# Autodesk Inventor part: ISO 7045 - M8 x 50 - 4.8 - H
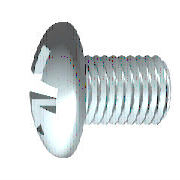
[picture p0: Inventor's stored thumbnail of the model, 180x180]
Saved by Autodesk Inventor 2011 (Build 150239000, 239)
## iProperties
IsCustomPart: 0
Created: 2010-02
Part Number: ISO 7045 - M8 x 50 - 4.8 - H
Material: Stainless Steel, 440C
Description: Cross Recessed Pan Head Machine Screw
Document SubType Name: Modeling
Standard: ISO 7045
Designer: R. Koolhoven
Standard Revision: 1994
Standards Organization: DIN
Language: en-US
Size Designation: M8 x 50 - 4.8 - H
Categories: <MemberInstance><Categories><Category DisplayName="Fasteners" InternalName="e4da775c-781d-43d5-af7c-5136215cf5a6" Mnemonic="FSTN"><Category DisplayName="Bolts"
Density: 7.75 g/cm^3
Mass: 25.2934 g
Surface Area: 18.7499 cm^2
Volume: 3.26367 cm^3
Author: R. Koolhoven
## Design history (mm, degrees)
body "Solid1"
workplane "Work Plane3"
sketch "Sketch2"
  geometry: L1 (-11.037, 0)-(11.037, 0) reference; L2 (0, -11.037)-(0, 11.037) reference; L3 (0, 4.5)-(0, 0); L4 (0, 0)-(4.5, 0); L5 (0, 0)-(5.574, 5.574); L6 (1.21, 4.334)-(0.822, 1.343); L7 (4.334, 1.21)-(1.343, 0.822); L8 (1.21, -4.334)-(0.822, -1.343); L9 (4.334, -1.21)-(1.343, -0.822); L10 (-1.21, 4.334)-(-0.822, 1.343); L11 (-4.334, 1.21)-(-1.343, 0.822); L12 (-4.334, -1.21)-(-1.343, -0.822); L13 (-1.21, -4.334)-(-0.822, -1.343); A1 r 1.35 centre (0, 0) between (1.35, 0) and (0, 1.35); A2 r 4.5 centre (0, 0) between (4.5, 0) and (4.334, 1.21); A3 r 4.5 centre (0, 0) between (1.21, 4.334) and (0, 4.5); A4 r 4.5 centre (0, 0) between (4.334, 1.21) and (1.21, 4.334); A5 r 4.5 centre (0, 0) between (0, -4.5) and (1.21, -4.334); A6 r 4.5 centre (0, 0) between (1.21, -4.334) and (4.334, -1.21); A7 r 4.5 centre (0, 0) between (4.334, -1.21) and (4.5, 0); A8 r 4.5 centre (0, 0) between (-4.334, 1.21) and (-4.5, 0); A9 r 4.5 centre (0, 0) between (-1.21, 4.334) and (-4.334, 1.21); A10 r 4.5 centre (0, 0) between (0, 4.5) and (-1.21, 4.334); A11 r 4.5 centre (0, 0) between (-4.5, 0) and (-4.334, -1.21); A12 r 4.5 centre (0, 0) between (-4.334, -1.21) and (-1.21, -4.334); A13 r 4.5 centre (0, 0) between (-1.21, -4.334) and (0, -4.5); A14 r 1.575 centre (0, 0) between (1.575, 0) and (0, 1.575); A15 r 0.465 centre (1.284, 1.284) between (0.822, 1.343) and (1.343, 0.822); A16 r 0.465 centre (1.284, -1.284) between (1.343, -0.822) and (0.822, -1.343); A17 r 0.465 centre (-1.284, 1.284) between (-1.343, 0.822) and (-0.822, 1.343); A18 r 0.465 centre (-1.284, -1.284) between (-0.822, -1.343) and (-1.343, -0.822); 1 further point
  constraints: 38 point on circle, 22 end point, 19 symmetric about line, 18 centre point, 4 coincident, 3 collinear, 3 point on line, 3 tangent, 1 perpendicular, 21 other
  dimensions: "d4" = 45 deg angle of L5 L4; "d5" = 2.7 diameter of A1 (= 0.3 x SDM); "d6" = 9 diameter of A4 (= SDM); "d7" = 1.21 distance from line of L6.start L3 (= 0.5 x SBR); "d14" = 3.15 diameter of A14 (= 0.35 x SDM)
extrude "Slot" join sketch "Sketch2" taper "d15" = 5 deg; stored distance "d54" = 10
revolve "Cut" stored, may be unused: angle "d56" = 90 deg
revolve "Body" stored, may be unused: angle "d18" = 90 deg
sketch "Sketch1"
  geometry: L1 (50, 0)-(50, 4); L2 (50, 4)-(12, 4); L3 (3.962, 5.08)-(3.962, 5.08); L4 (-6, 0)-(-6, 7.79); L5 (-5.317, 4.159)-(-2.996, 3.002); L6 (-2.996, 3.002)-(-1.4, 0); L7 (-1.4, 0)-(50, 0); L8 (-17.977, 0)-(61.33, 0) reference; L9 (0, -1.62)-(0, 9.723) reference; L10 (-5.317, 4.159)-(-6, 4.5); L11 (-3.337, 7.883)-(-6, 7.79); L12 (-3.337, 7.883)-(0, 8); L13 (0, 8)-(0, 4.062); L14 (0.4, 3.662)-(11.233, 3.662); L15 (11.233, 3.662)-(12, 4); L16 (12, 4)-(0, 4); A1 r 13 centre (7, 0) between (-3.337, 7.883) and (-6, 0); A2 r 0.4 centre (0.4, 4.062) between (0, 4.062) and (0.4, 3.662); 1 further point
  constraints: 28 end point, 7 point on line, 6 point on circle, 4 collinear, 3 parallel, 3 tangent, 2 centre point, 2 perpendicular, 1 horizontal
  dimensions: "d1" = 8 diameter of L2 L7 (= GD); "d2" = 4.6 distance from line of L6.end L4 (= STI); "d11" = 9 diameter of L10.end L7 (= SDM); "d12" = 62 deg angle of L6 L7; "d13" = 26.5 deg angle of L5 L7; "d17" = 16 diameter of L12.end L7 (= KOD); "d19" = 2 deg angle of L12 L7 (= KEWI); "d20" = 6 distance between parallel lines of L4 L13 (= KOH); "d21" = 13 radius of A1 (= KR); "d23" = 7.32342 diameter of L14 L7 (= BDM); "d24" = 38 distance of L1.end L2.end (= GEL); "d25" = 0.76681 horizontal distance of L14.end L2.end (= GAL); "d28" = 50 distance between parallel lines of L1 L13 (= NLG); "d81" = 0.4 radius of A2 (= R)
workplane "Work Plane1"
fillet "Fillet1" dims "d29" = 2.6 (= RR)
fillet "Fillet2" dims "d16" = 0.484 (= 0.2 x SBR)
feature "Thread" dims "d8" = 38 (= GEL), "d9" = 0
chamfer "Chamfer1" distance "d26" = 0.76681 (= -0.5 x SPD + 0.5 x GD); stored, may be unused: second distance "d27" = 0.76691 (computed from GUL), angle "d78" = 45 deg
other parameters: "GD" = 8 [user parameter; used in 2 equation terms], "NLG" = 50 [user parameter; used in 1 equation term], "GEL" = 38 [user parameter; used in 2 equation terms], "KOD" = 16 [user parameter; used in 1 equation term], "KOH" = 6 [user parameter; used in 2 equation terms], "SDM" = 9 [user parameter; used in 4 equation terms], "STI" = 4.6 [user parameter; used in 1 equation term], "SBR" = 2.42 [user parameter; used in 2 equation terms], "GAL" = 0.76681 (= 0.61345 x PTC) [user parameter; used in 1 equation term], "SPD" = 6.46637 (= NND - 1.2269 x PTC) [user parameter; used in 1 equation term], "KEWI" = 2 deg [user parameter; used in 1 equation term], "d3" = -6 (= -KOH), "d10" = 0, "KR" = 13 [user parameter; used in 1 equation term], "BDM" = 7.32342 [user parameter; used in 1 equation term], "GUL" = 0.76681 (= 0.61345 x PTC) [user parameter; used in 1 equation term], "RR" = 2.6 [user parameter; used in 1 equation term], "d79" = 0, "d80" = 0, "R" = 0.4 [user parameter; used in 1 equation term], "PTC" = 1.25 [user parameter; used in 5 equation terms], "THREADDIA" = 8 [user parameter; used in 1 equation term], "TOA" = 30 deg [user parameter], "TPU" = 8 (computed from PTC) [user parameter], "NND" = 8 [user parameter; used in 1 equation term], "GD1" = 6.46637 (= THREADDIA - 1.2269 x PTC) [user parameter]
